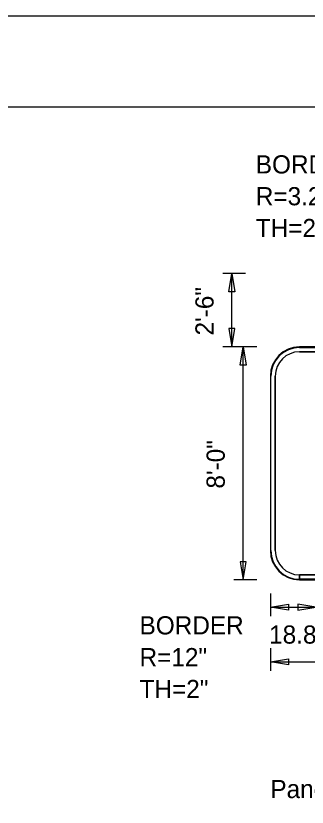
# Model space of a CAD drawing. Extents: x 1806251 to 1809821, y 414895 to 422886.
# Drawn here: x 1809675.736 to 1809676.937, y 414920.964 to 414924.227 of the extents above; entities that cross this region are included whole.
import ezdxf

# ---------------------------------------------------------------- set-up
doc = ezdxf.new("R2010")
doc.units = 0
for name, color, linetype in [('GSBWFILL', 7, 'Continuous'), ('GSCOLORFILL', 7, 'Continuous'), ('GSDIMS', 7, 'Continuous'), ('GSOUTLINE', 7, 'Continuous'), ('GSSHT', 7, 'Continuous')]:
    doc.layers.add(name, color=color, linetype=linetype)

msp = doc.modelspace()

# ---------------------------------------------------------------- linework, layer by layer
at = {"layer": 'GSBWFILL'}
for p, q in [((1809678.286, 414922.8615), (1809676.905, 414922.8615)), ((1809676.905, 414922.8415), (1809678.286, 414922.8415)), ((1809676.785, 414922.7415), (1809676.785, 414922.0215)), ((1809676.805, 414922.0215), (1809676.805, 414922.7415)), ((1809676.905, 414921.9015), (1809676.905, 414921.9215)), ((1809678.286, 414921.9215), (1809676.9052, 414921.9215)), ((1809676.9052, 414921.9215), (1809676.9052, 414921.9015)), ((1809676.9052, 414921.9015), (1809678.286, 414921.9015))]:
    msp.add_line(p, q, dxfattribs=at)
for centre, radius, start, end in [((1809676.905, 414922.7415), 0.12, 90, 180), ((1809676.905, 414922.7415), 0.1, 90, 180), ((1809676.905, 414922.0215), 0.12, 180, 270), ((1809676.905, 414922.0215), 0.1, 180, 270)]:
    msp.add_arc(centre, radius, start, end, dxfattribs=at)
at = {"layer": 'GSCOLORFILL'}
for p, q in [((1809678.286, 414922.8615), (1809676.905, 414922.8615)), ((1809678.286, 414922.8615), (1809676.905, 414922.8615)), ((1809678.286, 414922.8615), (1809676.905, 414922.8615)), ((1809676.905, 414922.8595), (1809678.286, 414922.8595)), ((1809676.905, 414922.8415), (1809678.286, 414922.8415)), ((1809676.785, 414922.7415), (1809676.785, 414922.0215)), ((1809676.785, 414922.7415), (1809676.785, 414922.0215)), ((1809676.785, 414922.7415), (1809676.785, 414922.0215)), ((1809676.787, 414922.0215), (1809676.787, 414922.7415)), ((1809676.805, 414922.0215), (1809676.805, 414922.7415)), ((1809676.905, 414921.9015), (1809676.905, 414921.9215)), ((1809676.905, 414921.9015), (1809676.905, 414921.9035)), ((1809678.286, 414921.9035), (1809676.905, 414921.9035)), ((1809676.905, 414921.9035), (1809676.905, 414921.9015)), ((1809676.905, 414921.9015), (1809678.286, 414921.9015)), ((1809676.905, 414921.9015), (1809678.286, 414921.9015)), ((1809678.286, 414921.9215), (1809676.9052, 414921.9215)), ((1809676.9052, 414921.9215), (1809676.9052, 414921.9015)), ((1809676.9052, 414921.9015), (1809678.286, 414921.9015))]:
    msp.add_line(p, q, dxfattribs=at)
for centre, radius, start, end in [((1809676.905, 414922.7415), 0.12, 90, 180), ((1809676.905, 414922.7415), 0.12, 90, 180), ((1809676.905, 414922.7415), 0.12, 90, 180), ((1809676.905, 414922.7415), 0.118, 90, 180), ((1809676.905, 414922.7415), 0.1, 90, 180), ((1809676.905, 414922.0215), 0.12, 180, 270), ((1809676.905, 414922.0215), 0.12, 180, 270), ((1809676.905, 414922.0215), 0.12, 180, 270), ((1809676.905, 414922.0215), 0.118, 180, 270), ((1809676.905, 414922.0215), 0.1, 180, 270)]:
    msp.add_arc(centre, radius, start, end, dxfattribs=at)
at = {"layer": 'GSDIMS'}
for p, q in [((1809676.6828, 414923.164), (1809676.589, 414923.164)), ((1809676.6265, 414922.862), (1809676.6265, 414923.164)), ((1809676.6828, 414922.862), (1809676.589, 414922.862)), ((1809676.7288, 414922.862), (1809676.635, 414922.862)), ((1809676.6725, 414921.901), (1809676.6725, 414922.862)), ((1809676.7288, 414921.901), (1809676.635, 414921.901)), ((1809676.785, 414921.8447), (1809676.785, 414921.751)), ((1809676.785, 414921.7885), (1809676.9729, 414921.7885)), ((1809676.785, 414921.6198), (1809676.785, 414921.526)), ((1809676.785, 414921.5635), (1809678.406, 414921.5635))]:
    msp.add_line(p, q, dxfattribs=at)
for points in [[(1809676.6265, 414923.164), (1809676.639, 414923.089), (1809676.614, 414923.089)], [(1809676.6265, 414922.862), (1809676.639, 414922.937), (1809676.614, 414922.937)], [(1809676.6725, 414922.862), (1809676.685, 414922.787), (1809676.66, 414922.787)], [(1809676.6725, 414921.901), (1809676.685, 414921.976), (1809676.66, 414921.976)], [(1809676.785, 414921.7885), (1809676.86, 414921.801), (1809676.86, 414921.776)], [(1809676.9729, 414921.7885), (1809676.8979, 414921.801), (1809676.8979, 414921.776)], [(1809676.785, 414921.5635), (1809676.86, 414921.576), (1809676.86, 414921.551)]]:
    msp.add_lwpolyline(points, close=True, dxfattribs=at)
at = {"layer": 'GSOUTLINE'}
for p, q in [((1809678.286, 414922.8615), (1809676.905, 414922.8615)), ((1809678.286, 414922.8415), (1809676.905, 414922.8415)), ((1809676.785, 414922.7415), (1809676.785, 414922.0215)), ((1809676.805, 414922.7415), (1809676.805, 414922.0215)), ((1809676.905, 414921.9215), (1809678.286, 414921.9215)), ((1809676.905, 414921.9015), (1809678.286, 414921.9015))]:
    msp.add_line(p, q, dxfattribs=at)
for centre, radius, start, end in [((1809676.905, 414922.7415), 0.12, 90, 180), ((1809676.905, 414922.7415), 0.1, 90, 180), ((1809676.905, 414922.0215), 0.12, 180, 270), ((1809676.905, 414922.0215), 0.1, 180, 270)]:
    msp.add_arc(centre, radius, start, end, dxfattribs=at)
at = {"layer": 'GSSHT'}
msp.add_line((1809672.1353, 414924.2272), (1809684.8895, 414924.2272), dxfattribs=at)
msp.add_lwpolyline([(1809672.6344, 414923.8521), (1809684.6385, 414923.8521), (1809684.6385, 414916.3484), (1809672.6344, 414916.3484)], close=True, dxfattribs=at)

# ---------------------------------------------------------------- texts
at = {"layer": 'GSDIMS'}
for s, p in [('BORDER', (1809676.725, 414923.577)), ('R=3.25"', (1809676.725, 414923.4458)), ('TH=2"', (1809676.725, 414923.3145)), ('BORDER', (1809676.246, 414921.676)), ('18.8"', (1809676.7799, 414921.638)), ('R=12"', (1809676.246, 414921.5448)), ('TH=2"', (1809676.246, 414921.4135)), ('Panel Style: guide_fwy_overhead.ssi', (1809676.785, 414921.001))]:
    msp.add_text(s, height=0.075, dxfattribs=at).set_placement(p)
for s, p in [('2\'-6"', (1809676.551, 414922.909)), ('8\'-0"', (1809676.597, 414922.2775))]:
    msp.add_text(s, height=0.075, rotation=90, dxfattribs=at).set_placement(p)

doc.saveas('drawing.dxf')
